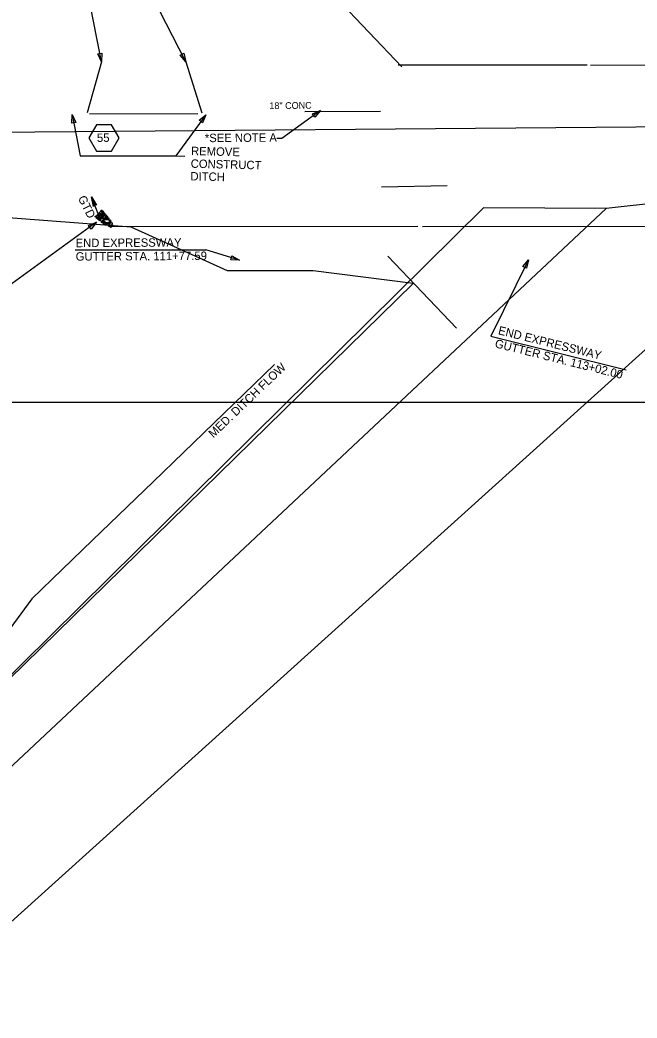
# Model space of a CAD drawing. Extents: x 2384780 to 2405432, y 547869 to 573706.
# Drawn here: x 2397544 to 2397910, y 558941 to 559532 of the extents above; entities that cross this region are included whole.
import ezdxf

# ---------------------------------------------------------------- set-up
doc = ezdxf.new("R2010")
doc.units = 0
for name, color, linetype in [('Old_Level_1', 7, 'Continuous'), ('Old_Level_10', 7, 'Continuous'), ('Old_Level_18', 7, 'Continuous'), ('Old_Level_19', 7, 'Continuous'), ('Old_Level_26', 7, 'Continuous'), ('Old_Level_5', 7, 'Continuous'), ('Old_Level_62', 7, 'Continuous'), ('Old_Level_63', 7, 'Continuous'), ('Prop Drainage Box Number Symbol CELL', 7, 'Continuous'), ('Prop Erosion Rip Rap Class B Label', 7, 'Continuous'), ('Prop Plan Preparation Grade to Drain Label', 7, 'Continuous')]:
    doc.layers.add(name, color=color, linetype=linetype)

msp = doc.modelspace()

# ---------------------------------------------------------------- linework, layer by layer
at = {"layer": 'Old_Level_1'}
msp.add_line((2397585.62, 559476.72), (2397649.91, 559476.79), dxfattribs=at)
at = {"layer": 'Old_Level_10'}
msp.add_lwpolyline([(2397713.27, 559478.06), (2397758.3, 559478.26)], dxfattribs=at)
at = {"layer": 'Old_Level_18'}
for p, q in [((2397592.73, 559507.47), (2397561.62, 559665.33)), ((2397642.73, 559507.52), (2397561.62, 559665.33)), ((2397770.91, 559504.49), (2397727.32, 559550.33)), ((2397592.73, 559507.47), (2397584.12, 559477.29)), ((2397642.73, 559507.52), (2397652.15, 559477.19)), ((2397880.9, 559505.55), (2397768.73, 559505.42)), ((2397882.88, 559505.55), (2398091.24, 559505.8)), ((2397780.32, 559409.93), (2397598.84, 559409.72)), ((2397783.13, 559409.94), (2397998.34, 559410.19))]:
    msp.add_line(p, q, dxfattribs=at)
for points in [[(2397592.99, 559512.61), (2397592.73, 559507.47), (2397590.53, 559512.13)], [(2397641.55, 559512.54), (2397642.73, 559507.52), (2397639.33, 559511.4)]]:
    msp.add_lwpolyline(points, close=True, dxfattribs=at)
at = {"layer": 'Old_Level_19'}
msp.add_line((2397758.81, 559433.38), (2397797.78, 559434.23), dxfattribs=at)
msp.add_lwpolyline([(2397695.28, 559327.99), (2397659.29, 559293.28), (2397623.29, 559258.57), (2397587.3, 559223.86), (2397551.31, 559189.15), (2397520.14, 559146.85)], dxfattribs=at)
at = {"layer": 'Old_Level_5'}
for p, q in [((2397575.28, 559476.19), (2397580.14, 559451.78)), ((2397654.59, 559476.03), (2397636.74, 559451.65)), ((2397722.57, 559478.56), (2397699.7, 559461.99)), ((2397699.7, 559461.99), (2397696.76, 559461.98)), ((2397580.14, 559451.78), (2397636.74, 559451.65)), ((2397636.74, 559451.65), (2397642.24, 559451.57)), ((2397589.83, 559412.32), (2397499.11, 559346.76)), ((2397577.1, 559396.03), (2397654.54, 559396.05)), ((2397674.51, 559389.94), (2397654.54, 559396.05)), ((2397845.94, 559390.11), (2397823.77, 559344.86)), ((2397823.77, 559344.86), (2397903.9, 559324.88))]:
    msp.add_line(p, q, dxfattribs=at)
for points in [[(2397575.03, 559471.04), (2397575.28, 559476.19), (2397577.48, 559471.53)], [(2397650.55, 559472.82), (2397654.59, 559476.03), (2397652.53, 559471.3)], [(2397717.79, 559476.64), (2397722.57, 559478.56), (2397719.25, 559474.62)], [(2397585.05, 559410.38), (2397589.83, 559412.32), (2397586.53, 559408.36)], [(2397670.03, 559392.49), (2397674.51, 559389.94), (2397669.36, 559390.08)], [(2397842.68, 559386.12), (2397845.94, 559390.11), (2397844.94, 559385.06)]]:
    msp.add_lwpolyline(points, close=True, dxfattribs=at)
at = {"layer": 'Old_Level_62'}
for points in [[(2397220.17, 559463.12), (2398218.71, 559471.56), (2398237.6, 559142.52), (2397764.97, 558556.02), (2397466.68, 558691.91), (2397374.16, 558981.45), (2397777.58, 559376.08)], [(2397777.58, 559376.08), (2397718.22, 559383.53), (2397667.47, 559383.58), (2397610.22, 559409.47), (2397464.38, 559420.58), (2397378.35, 559425.77), (2397267.37, 559426.89), (2397220.17, 559463.12)]]:
    msp.add_lwpolyline(points, dxfattribs=at)
for points in [[(2397403.1, 558875.13), (2397978.41, 559393.67), (2397960.06, 559428.01), (2397892.02, 559420.52), (2397386.42, 558946.65)], [(2397386.42, 558946.65), (2397892.02, 559420.52), (2397819.35, 559420.85), (2397374.16, 558981.45)]]:
    msp.add_lwpolyline(points, close=True, dxfattribs=at)
at = {"layer": 'Old_Level_63'}
msp.add_line((2397803.29, 559349.56), (2397762.63, 559392.32), dxfattribs=at)
msp.add_lwpolyline([(2396166.58, 559305.72), (2404966.58, 559305.72), (2404966.58, 573705.72), (2396166.58, 573705.72)], close=True, dxfattribs=at)
at = {"layer": 'Prop Drainage Box Number Symbol CELL'}
msp.add_lwpolyline([(2397603.12, 559462.32), (2397598.65, 559470.07), (2397589.7, 559470.07), (2397585.23, 559462.32), (2397589.7, 559454.57), (2397598.65, 559454.57)], close=True, dxfattribs=at)
at = {"layer": 'Prop Erosion Rip Rap Class B Label'}
for points in [[(2397593.07, 559419.45), (2397592.93, 559419.16), (2397592.64, 559418.77), (2397592.31, 559418.92), (2397592.16, 559419.14), (2397592.64, 559419.57), (2397592.95, 559419.59), (2397593.07, 559419.45)], [(2397588.99, 559415.91), (2397589.28, 559415.97), (2397589.71, 559415.72), (2397589.75, 559415.4), (2397589.59, 559415.29), (2397589.04, 559415.5), (2397588.95, 559415.69), (2397588.99, 559415.91)], [(2397591.16, 559415.09), (2397590.65, 559415.13), (2397589.71, 559415.55), (2397589.64, 559416.26), (2397590.08, 559416.57), (2397591.18, 559416.02), (2397591.38, 559415.58), (2397591.21, 559415.04)], [(2397590.6, 559415.09), (2397590.48, 559414.8), (2397590.13, 559414.56), (2397589.75, 559414.65), (2397589.69, 559414.86), (2397590.09, 559415.31), (2397590.46, 559415.22), (2397590.6, 559415.09)], [(2397591.57, 559417.26), (2397591.38, 559416.94), (2397590.96, 559416.46), (2397590.43, 559416.66), (2397590.27, 559416.91), (2397590.96, 559417.54), (2397591.35, 559417.51), (2397591.57, 559417.26)], [(2397590.61, 559414.01), (2397590.62, 559414.36), (2397590.85, 559414.74), (2397591.17, 559414.83), (2397591.4, 559414.63), (2397591.06, 559414.13), (2397590.81, 559413.95), (2397590.61, 559414.01)], [(2397590.99, 559416.59), (2397591.28, 559416.63), (2397591.73, 559416.4), (2397591.74, 559416.08), (2397591.62, 559415.94), (2397591.01, 559416.17), (2397590.92, 559416.4), (2397590.99, 559416.59)], [(2397591.27, 559413.83), (2397591.56, 559413.89), (2397592, 559413.64), (2397592.04, 559413.33), (2397591.88, 559413.22), (2397591.33, 559413.43), (2397591.24, 559413.61), (2397591.27, 559413.83)], [(2397593.16, 559418.46), (2397592.88, 559418.02), (2397592.26, 559417.27), (2397591.5, 559417.48), (2397591.28, 559417.96), (2397592.13, 559418.81), (2397592.77, 559418.8), (2397593.16, 559418.46)], [(2397592.26, 559414.45), (2397592.15, 559414.14), (2397591.8, 559413.91), (2397591.42, 559413.99), (2397591.35, 559414.2), (2397591.75, 559414.65), (2397592.13, 559414.57), (2397592.26, 559414.45)], [(2397591.74, 559415.22), (2397591.98, 559415.25), (2397592.5, 559415.01), (2397592.51, 559414.7), (2397592.35, 559414.58), (2397591.76, 559414.81), (2397591.67, 559414.98), (2397591.74, 559415.22)], [(2397593.12, 559415.01), (2397592.69, 559415.14), (2397591.73, 559415.58), (2397591.69, 559416.26), (2397592.04, 559416.66), (2397593.11, 559416.07), (2397593.46, 559415.55), (2397593.16, 559415.11)], [(2397592.16, 559413.22), (2397592.27, 559413.75), (2397592.65, 559414.87), (2397593.61, 559414.88), (2397593.98, 559414.56), (2397593.35, 559413.21), (2397592.67, 559412.87), (2397592.08, 559413.12)], [(2397592.21, 559416.7), (2397592.3, 559417.08), (2397592.68, 559417.69), (2397593.11, 559417.71), (2397593.33, 559417.51), (2397592.95, 559416.75), (2397592.63, 559416.54), (2397592.21, 559416.7)], [(2397593.91, 559418.89), (2397593.78, 559418.61), (2397593.48, 559418.22), (2397593.16, 559418.36), (2397593.01, 559418.58), (2397593.48, 559419.01), (2397593.79, 559419.03), (2397593.91, 559418.89)], [(2397593.17, 559416.47), (2397593.49, 559416.5), (2397593.92, 559416.25), (2397593.93, 559415.93), (2397593.79, 559415.81), (2397593.24, 559416.05), (2397593.12, 559416.25), (2397593.17, 559416.47)], [(2397594.15, 559418.24), (2397594.02, 559417.96), (2397593.73, 559417.56), (2397593.41, 559417.71), (2397593.26, 559417.93), (2397593.73, 559418.36), (2397594.04, 559418.38), (2397594.15, 559418.24)], [(2397593.4, 559417.2), (2397593.59, 559417.13), (2397594.09, 559416.96), (2397594.07, 559416.58), (2397593.94, 559416.44), (2397593.31, 559416.7), (2397593.33, 559416.96), (2397593.4, 559417.2)], [(2397595.42, 559415.85), (2397595.14, 559415.38), (2397594.4, 559414.69), (2397593.75, 559414.87), (2397593.47, 559415.34), (2397594.34, 559416.17), (2397595.06, 559416.24), (2397595.42, 559415.85)], [(2397594.54, 559414.14), (2397594.43, 559413.83), (2397594.08, 559413.6), (2397593.69, 559413.68), (2397593.63, 559413.89), (2397594.03, 559414.34), (2397594.4, 559414.26), (2397594.54, 559414.14)], [(2397593.9, 559417.71), (2397594.23, 559417.68), (2397594.69, 559417.46), (2397594.68, 559417.17), (2397594.56, 559417.04), (2397593.95, 559417.26), (2397593.86, 559417.5), (2397593.9, 559417.71)], [(2397594.09, 559416.33), (2397594.18, 559416.54), (2397594.43, 559416.97), (2397594.74, 559417), (2397594.86, 559416.9), (2397594.7, 559416.38), (2397594.42, 559416.24), (2397594.2, 559416.28)], [(2397594.46, 559413.84), (2397595.29, 559414.05), (2397597.02, 559413.88), (2397597.49, 559412.77), (2397597.14, 559412.02), (2397594.99, 559412.17), (2397594.34, 559412.9), (2397594.29, 559413.84)], [(2397594.64, 559414.73), (2397594.91, 559414.78), (2397595.34, 559414.51), (2397595.39, 559414.23), (2397595.23, 559414.06), (2397594.66, 559414.3), (2397594.57, 559414.54), (2397594.64, 559414.73)], [(2397594.92, 559416.78), (2397595.2, 559416.83), (2397595.64, 559416.59), (2397595.65, 559416.27), (2397595.53, 559416.14), (2397594.93, 559416.36), (2397594.84, 559416.59), (2397594.92, 559416.78)], [(2397595.07, 559414.82), (2397595.13, 559415.06), (2397595.3, 559415.56), (2397595.68, 559415.49), (2397595.8, 559415.38), (2397595.57, 559414.77), (2397595.37, 559414.7), (2397595.07, 559414.82)], [(2397595.54, 559415.95), (2397595.82, 559416), (2397596.27, 559415.76), (2397596.28, 559415.44), (2397596.15, 559415.3), (2397595.56, 559415.53), (2397595.47, 559415.76), (2397595.54, 559415.95)], [(2397596.47, 559415.1), (2397596.44, 559414.73), (2397596.14, 559414.09), (2397595.7, 559414.05), (2397595.47, 559414.25), (2397595.78, 559415.07), (2397596.18, 559415.23), (2397596.47, 559415.1)], [(2397597.19, 559414.61), (2397597.05, 559414.32), (2397596.76, 559413.93), (2397596.44, 559414.08), (2397596.29, 559414.3), (2397596.76, 559414.73), (2397597.07, 559414.75), (2397597.19, 559414.61)], [(2397597.26, 559413.75), (2397597.56, 559413.74), (2397598, 559413.51), (2397598.04, 559413.22), (2397597.89, 559413.05), (2397597.29, 559413.33), (2397597.21, 559413.54), (2397597.26, 559413.75)], [(2397592.67, 559412.21), (2397592.66, 559412.47), (2397592.84, 559412.86), (2397593.19, 559412.96), (2397593.43, 559412.75), (2397593.09, 559412.24), (2397592.82, 559412.09), (2397592.67, 559412.21)], [(2397593.22, 559412.4), (2397593.51, 559412.44), (2397593.94, 559412.19), (2397593.97, 559411.89), (2397593.82, 559411.78), (2397593.27, 559412), (2397593.18, 559412.18), (2397593.22, 559412.4)], [(2397593.51, 559413.17), (2397593.79, 559413.19), (2397594.19, 559412.93), (2397594.24, 559412.63), (2397594.09, 559412.46), (2397593.53, 559412.74), (2397593.47, 559412.95), (2397593.51, 559413.17)], [(2397595.07, 559411.89), (2397594.89, 559411.51), (2397594.5, 559411.06), (2397593.96, 559411.23), (2397593.83, 559411.55), (2397594.47, 559412.14), (2397594.86, 559412.08), (2397595.07, 559411.89)], [(2397594.82, 559411.37), (2397595.11, 559411.43), (2397595.54, 559411.18), (2397595.57, 559410.86), (2397595.42, 559410.75), (2397594.87, 559410.98), (2397594.77, 559411.16), (2397594.82, 559411.37)], [(2397595.11, 559411.89), (2397595.42, 559411.9), (2397595.82, 559411.64), (2397595.88, 559411.35), (2397595.73, 559411.18), (2397595.12, 559411.46), (2397595.06, 559411.67), (2397595.11, 559411.89)], [(2397595.65, 559412.12), (2397595.94, 559412.16), (2397596.37, 559411.92), (2397596.41, 559411.61), (2397596.26, 559411.5), (2397595.7, 559411.72), (2397595.61, 559411.9), (2397595.65, 559412.12)], [(2397597.58, 559411.6), (2397597.34, 559411.16), (2397596.67, 559410.4), (2397595.93, 559410.59), (2397595.75, 559411), (2397596.63, 559411.88), (2397597.21, 559411.91), (2397597.58, 559411.6)], [(2397596.98, 559410.69), (2397597.33, 559410.63), (2397597.92, 559410.41), (2397598.01, 559409.87), (2397597.74, 559409.57), (2397596.94, 559410.02), (2397596.84, 559410.36), (2397596.98, 559410.69)], [(2397598.17, 559412.28), (2397598.03, 559412.11), (2397597.73, 559411.77), (2397597.42, 559411.88), (2397597.29, 559412.01), (2397597.68, 559412.46), (2397598.04, 559412.54), (2397598.17, 559412.28)], [(2397599.07, 559411.93), (2397598.94, 559411.51), (2397598.52, 559410.57), (2397597.8, 559410.5), (2397597.43, 559410.89), (2397598, 559411.98), (2397598.61, 559412.21), (2397598.98, 559412.02)], [(2397597.52, 559413.08), (2397597.8, 559413.13), (2397598.25, 559412.89), (2397598.26, 559412.57), (2397598.14, 559412.43), (2397597.55, 559412.67), (2397597.45, 559412.89), (2397597.52, 559413.08)], [(2397597.96, 559409.37), (2397598.04, 559409.6), (2397598.22, 559410.15), (2397598.55, 559410.05), (2397598.69, 559409.94), (2397598.5, 559409.35), (2397598.19, 559409.18), (2397597.96, 559409.37)], [(2397598.53, 559410.22), (2397598.62, 559410.43), (2397598.77, 559410.95), (2397599.12, 559410.9), (2397599.26, 559410.77), (2397599.06, 559410.14), (2397598.75, 559410.02), (2397598.53, 559410.22)]]:
    msp.add_lwpolyline(points, dxfattribs=at)
at = {"layer": 'Prop Plan Preparation Grade to Drain Label'}
msp.add_line((2397591.13, 559416.29), (2397586.7, 559427.44), dxfattribs=at)
msp.add_lwpolyline([(2397587.92, 559421.78), (2397586.7, 559427.44), (2397589.69, 559422.49), (2397588.54, 559422.8)], close=True, dxfattribs=at)

# ---------------------------------------------------------------- texts
at = {"layer": 'Old_Level_19'}
msp.add_text('MED. DITCH FLOW', height=5, rotation=43.62106, dxfattribs=at).set_placement((2397659.03, 559284.29))
at = {"layer": 'Old_Level_26'}
msp.add_text('18" CONC', height=4, rotation=0.71604, dxfattribs=at).set_placement((2397692.34, 559479.4))
at = {"layer": 'Old_Level_5'}
for s, rotation, p in [('*SEE NOTE A', 0.38738, (2397654.03, 559459.82)), ('REMOVE ', 358.60101, (2397645.76, 559452.18)), ('CONSTRUCT', 358.60101, (2397645.58, 559444.68)), ('DITCH', 358.60101, (2397645.4, 559437.19)), ('END EXPRESSWAY', 0.33177, (2397577.36, 559397.58)), ('GUTTER STA. 111+77.59', 0.33177, (2397577.41, 559389.58)), ('END EXPRESSWAY', 346.00008, (2397827.68, 559346.07)), ('GUTTER STA. 113+02.00', 346.00008, (2397825.74, 559338.31))]:
    msp.add_text(s, height=5, rotation=rotation, dxfattribs=at).set_placement(p)
at = {"layer": 'Prop Drainage Box Number Symbol CELL'}
msp.add_text('55', height=5, rotation=0.72632, dxfattribs=at).set_placement((2397590.04, 559459.93))
at = {"layer": 'Prop Plan Preparation Grade to Drain Label'}
msp.add_text('GTD', height=5, rotation=296.61579, dxfattribs=at).set_placement((2397578.58, 559426.68))

doc.saveas('drawing.dxf')
